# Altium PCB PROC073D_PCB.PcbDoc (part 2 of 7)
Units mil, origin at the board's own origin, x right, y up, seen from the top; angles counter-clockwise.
Board outline 2165.35 x 2695.12 mil, 8 copper layers (Top Layer, L2_GND, L3_SIGNAL 1, L4_SIGNAL 2, L5_SIGNAL 3, L6_SIGNAL 4, L7_GND, Bottom Layer), stack 56.1 mil thick; 414 components, 319 nets, 1353 pads, 1669 vias.
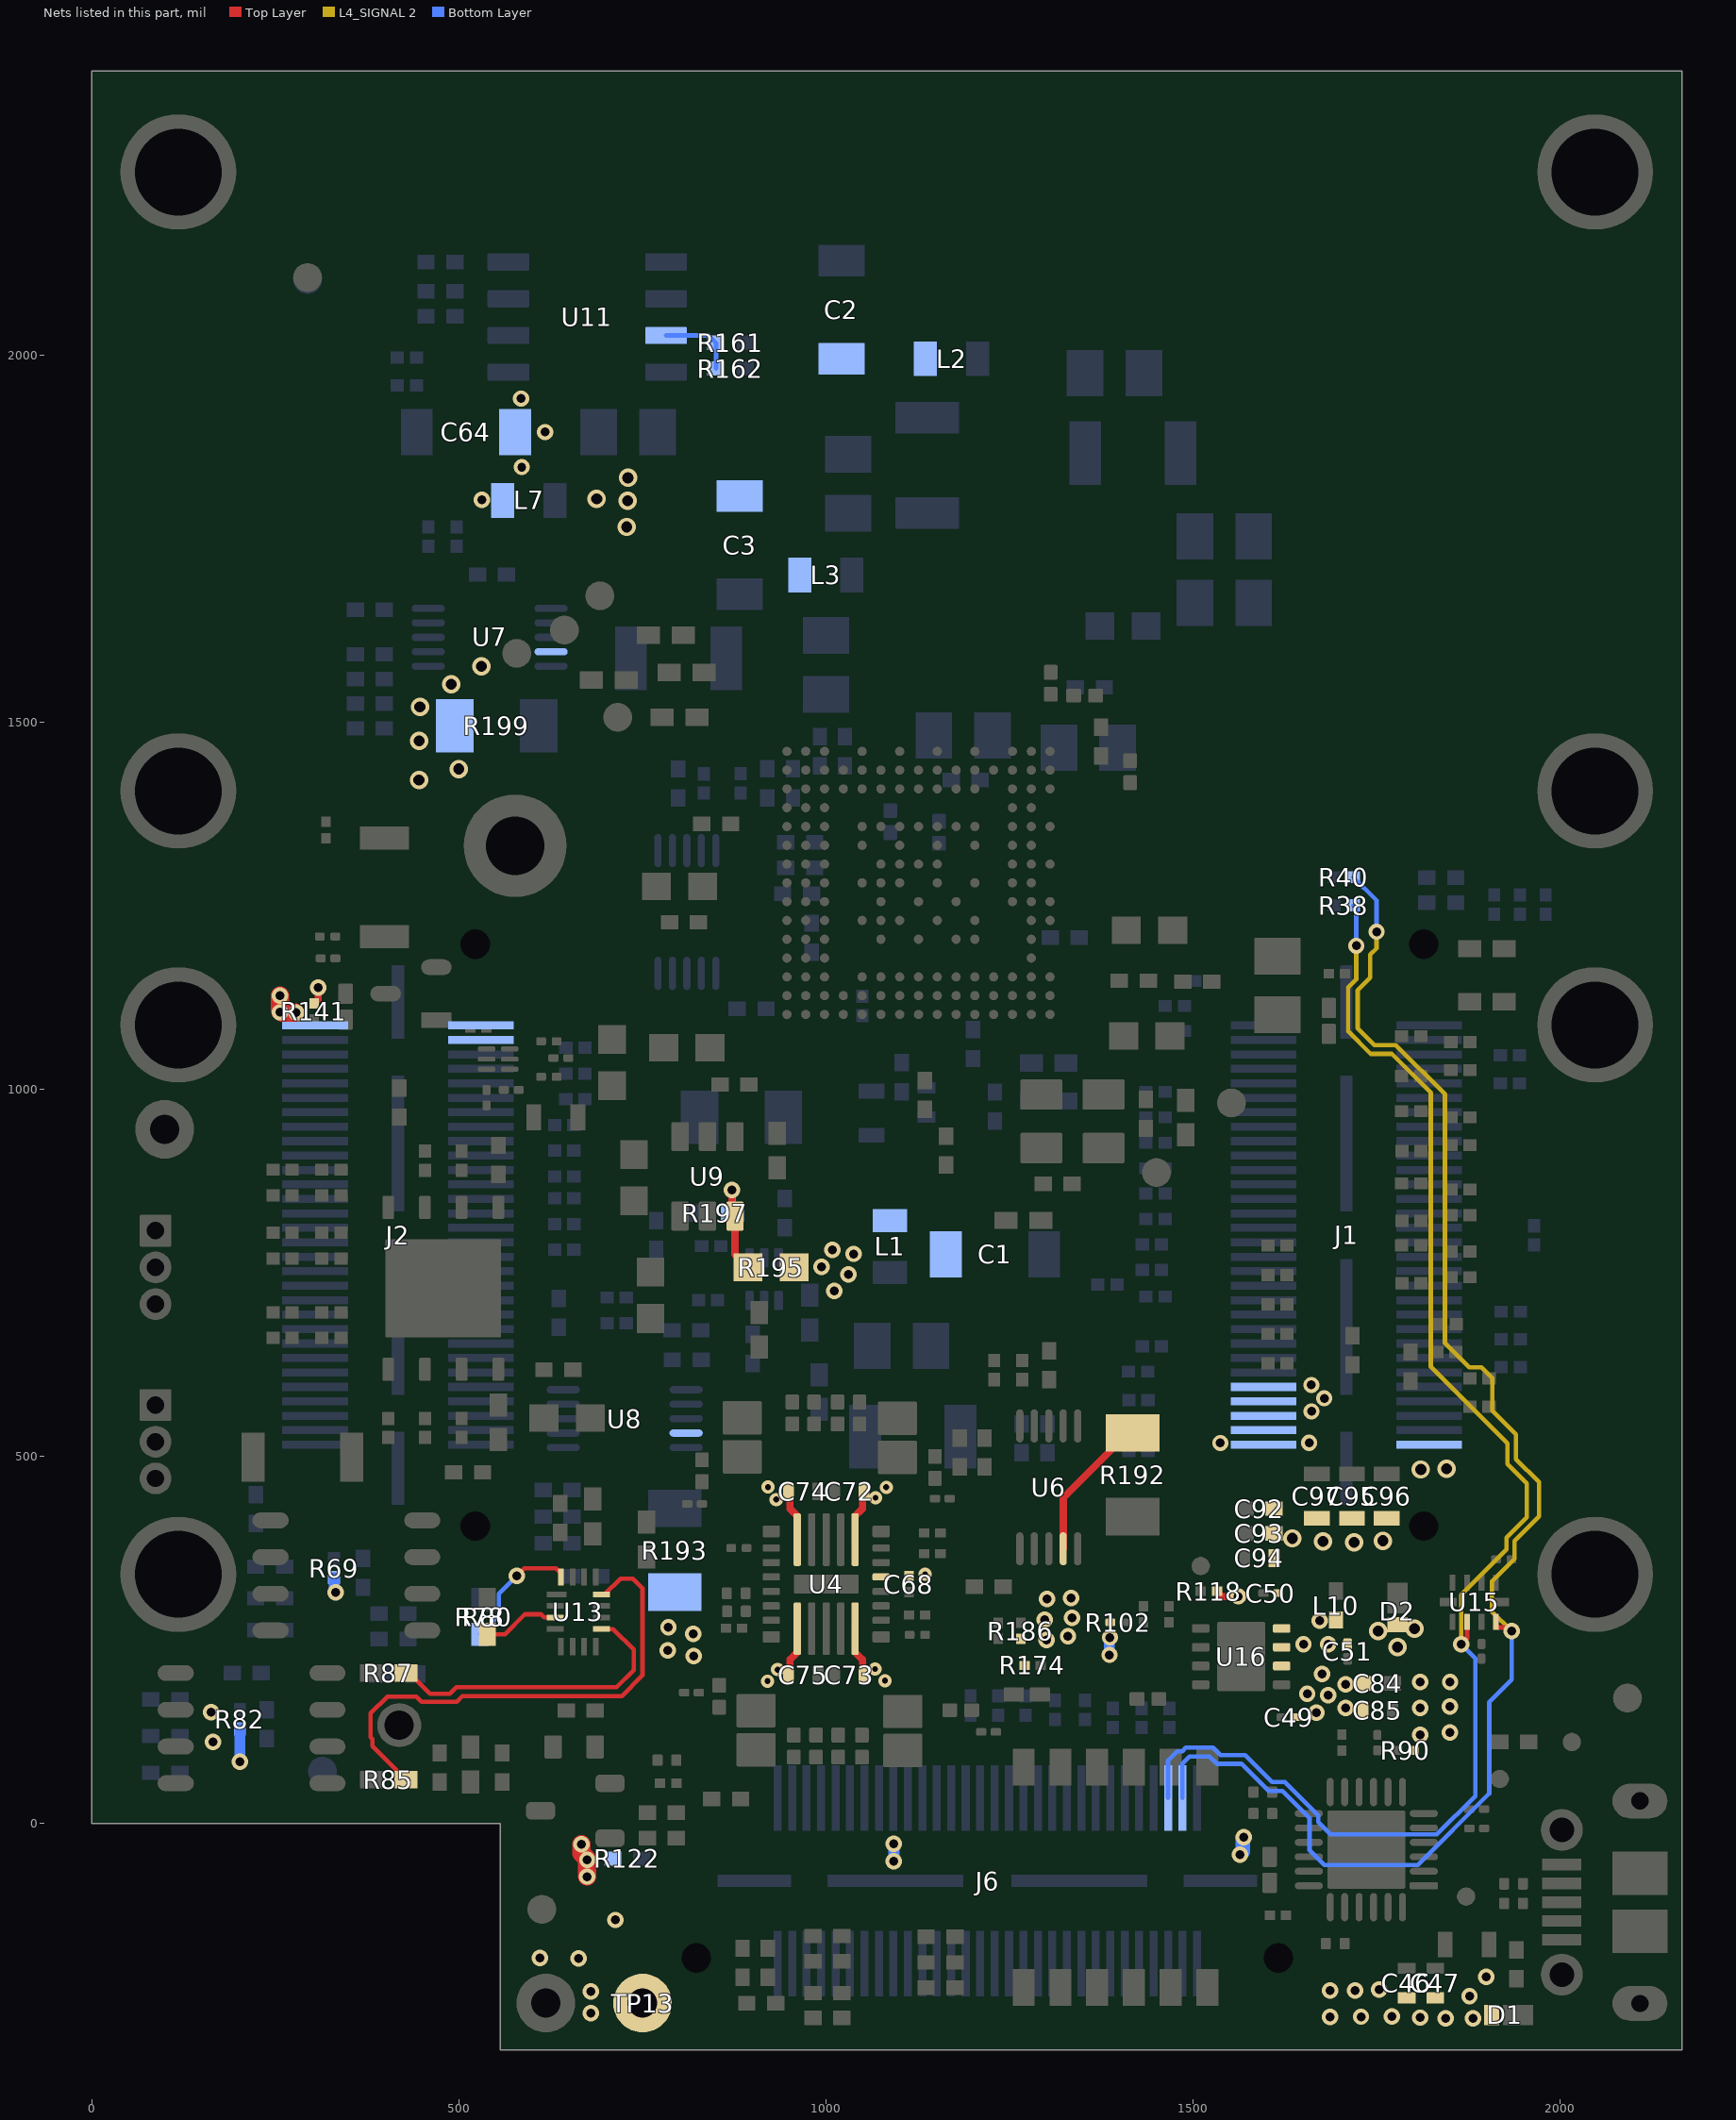
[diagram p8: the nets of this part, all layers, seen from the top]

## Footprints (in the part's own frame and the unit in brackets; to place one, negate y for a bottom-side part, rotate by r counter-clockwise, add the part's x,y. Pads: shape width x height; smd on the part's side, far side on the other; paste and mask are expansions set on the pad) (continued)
ABL0161B [mm] "BGA, 161-Balls, Body 10.4x10.4mm, Pitch 0.65mm"
  round 0.32 smd: A1(-4.55,4.55) A2(-3.9,4.55) A3(-3.25,4.55) A5(-1.95,4.55) A7(-0.65,4.55) A9(0.65,4.55) A10(1.3,4.55) A13(3.25,4.55) A14(3.9,4.55) A15(4.55,4.55) B1(-4.55,3.9) B2(-3.9,3.9) B3(-3.25,3.9) B4(-2.6,3.9) B5(-1.95,3.9) B6(-1.3,3.9) B7(-0.65,3.9) B8(0,3.9) B9(0.65,3.9) B10(1.3,3.9) B11(1.95,3.9) B12(2.6,3.9) B13(3.25,3.9) B14(3.9,3.9) B15(4.55,3.9) C1(-4.55,3.25) C2(-3.9,3.25) C3(-3.25,3.25) C4(-2.6,3.25) C5(-1.95,3.25) C6(-1.3,3.25) C7(-0.65,3.25) C8(0,3.25) C9(0.65,3.25) C13(3.25,3.25) C14(3.9,3.25) C15(4.55,3.25) D2(-3.9,2.6) D13(3.25,2.6) D14(3.9,2.6) D15(4.55,2.6) E1(-4.55,1.95) E2(-3.9,1.95) E3(-3.25,1.95) E5(-1.95,1.95) E6(-1.3,1.95) E8(0,1.95) E10(1.3,1.95) E11(1.95,1.95) E13(3.25,1.95) E14(3.9,1.95) E15(4.55,1.95) F2(-3.9,1.3) F3(-3.25,1.3) F5(-1.95,1.3) F9(0.65,1.3) F11(1.95,1.3) F13(3.25,1.3) F14(3.9,1.3) F15(4.55,1.3) G1(-4.55,0.65) G2(-3.9,0.65) G3(-3.25,0.65) G5(-1.95,0.65) G6(-1.3,0.65) G7(-0.65,0.65) G8(0,0.65) G10(1.3,0.65) G13(3.25,0.65) G14(3.9,0.65) G15(4.55,0.65) H2(-3.9,0) H3(-3.25,0) H5(-1.95,0) H7(-0.65,0) H9(0.65,0) H11(1.95,0) H13(3.25,0) H14(3.9,0) H15(4.55,0) J1(-4.55,-0.65) J2(-3.9,-0.65) J3(-3.25,-0.65) J5(-1.95,-0.65) J6(-1.3,-0.65) J7(-0.65,-0.65) J8(0,-0.65) J10(1.3,-0.65) J13(3.25,-0.65) J14(3.9,-0.65) J15(4.55,-0.65) K2(-3.9,-1.3) K3(-3.25,-1.3) K5(-1.95,-1.3) K7(-0.65,-1.3) K8(0,-1.3) K9(0.65,-1.3) K10(1.3,-1.3) K11(1.95,-1.3) K13(3.25,-1.3) K14(3.9,-1.3) K15(4.55,-1.3) L1(-4.55,-1.95) L2(-3.9,-1.95) L3(-3.25,-1.95) L5(-1.95,-1.95) L6(-1.3,-1.95) L8(0,-1.95) L10(1.3,-1.95) L13(3.25,-1.95) L14(3.9,-1.95) L15(4.55,-1.95) M2(-3.9,-2.6) M3(-3.25,-2.6) M14(3.9,-2.6) M15(4.55,-2.6) N1(-4.55,-3.25) N2(-3.9,-3.25) N3(-3.25,-3.25) N4(-2.6,-3.25) N5(-1.95,-3.25) N6(-1.3,-3.25) N7(-0.65,-3.25) N8(0,-3.25) N9(0.65,-3.25) N10(1.3,-3.25) N11(1.95,-3.25) N12(2.6,-3.25) N13(3.25,-3.25) N14(3.9,-3.25) N15(4.55,-3.25) P1(-4.55,-3.9) P2(-3.9,-3.9) P3(-3.25,-3.9) P4(-2.6,-3.9) P5(-1.95,-3.9) P6(-1.3,-3.9) P7(-0.65,-3.9) P8(0,-3.9) P9(0.65,-3.9) P10(1.3,-3.9) P11(1.95,-3.9) P12(2.6,-3.9) P13(3.25,-3.9) P14(3.9,-3.9) P15(4.55,-3.9) R1(-4.55,-4.55) R2(-3.9,-4.55) R3(-3.25,-4.55) R4(-2.6,-4.55) R5(-1.95,-4.55) R6(-1.3,-4.55) R7(-0.65,-4.55) R8(0,-4.55) R9(0.65,-4.55) R10(1.3,-4.55) R11(1.95,-4.55) R12(2.6,-4.55) R13(3.25,-4.55) R14(3.9,-4.55) R15(4.55,-4.55)
  silkscreen extent -5.3,-5.3 5.3,5.3, body extent -5.2,-5.2 5.2,5.2, height 0.62
APHHS1005_Green [mm] "SMD, 2-Leads, Body 1x0.5mm"
  rrect20% 0.7x0.5 smd: 1(-0.45,0) 2(0.45,0)
  silkscreen extent -0.8,-0.65 1.2,0.65, body extent -0.5,-0.25 0.5,0.25, height 0.5
AssemblyNote [mil] "Assembly Note"
AssemblyNoteLabel [mil] "Assembly Note for PCB Labels"
CE_Mark_5mm [mil] "Minimum text height for CE Mark"
  silkscreen extent -138,-98 138,98
CONN_105017-0001 [mm] "Molex Micro USB-B"
  rect 0.4x1.35 smd: 1(-1.3,1.35) 2(-0.65,1.35) 3(0,1.35) 4(0.65,1.35) 5(1.3,1.35)
  oval 1.2x1.9 hole 0.6 slot 1.3 at 90 deg: 6(-3.5,-1.35) 9(3.5,-1.35)
  rect 1.5x1.9 smd: 7(-1,-1.35) 8(1,-1.35)
  round 1.45 hole 0.85: 10(2.5,1.35) 11(-2.5,1.35)
  Top Layer region: 3.499,-0.399 2.299,-0.399 2.299,-2.299 3.499,-2.299
  Top Layer region: -3.5,-2.299 -2.3,-2.299 -2.3,-0.399 -3.5,-0.399
  silkscreen extent -4.1,-0.2 4.1,1.4, body extent -4.1,-3.93 4.1,1.5, height 2.72
D0008A_L [mm] "SOIC, 8-Leads, Body 4.9x3.9mm, Pitch 1.27mm, IPC High Density"
  oval 1.25x0.55 smd: 1(-2.625,1.905) 2(-2.625,0.635) 3(-2.625,-0.635) 4(-2.625,-1.905) 5(2.625,-1.905) 6(2.625,-0.635) 7(2.625,0.635) 8(2.625,1.905)
  silkscreen extent -3.1,-2.5 0.9,2.5, body extent -3,-2.45 3,2.45, height 1.63
DBV0006A_N [mm] "SOT23, 6-Leads, Body 2.9x1.6mm, Pitch 0.95mm, Lead Span 2.8mm, IPC Medium Density"
  rrect17% 1x0.6 smd: 1(-1.375,0.95) 2(-1.375,0) 3(-1.375,-0.95) 4(1.375,-0.95) 5(1.375,0) 6(1.375,0.95)
  silkscreen extent -1.68,-1.55 0.5,1.55, body extent -1.42,-1.46 1.42,1.46, height 1.12
DGS0010A_L [mm] "TSSOP, 10-Leads, Body 3x3mm, Pitch 0.5mm, IPC High Density"
  oval 1.15x0.25 smd: 1(-2.125,1) 2(-2.125,0.5) 3(-2.125,0) 4(-2.125,-0.5) 5(-2.125,-1) 6(2.125,-1) 7(2.125,-0.5) 8(2.125,0) 9(2.125,0.5) 10(2.125,1)
  silkscreen extent -2.65,-1.55 0.9,1.55, body extent -2.45,-1.5 2.45,1.5, height 0.96
DRB0008B [mm] "SON, 8-Leads, Body 3x3mm, Pitch 0.65mm, Thermal Pad 2.4x1.65mm, TI Recommended"
  rrect33% 0.6x0.3 smd: 1(-1.4,0.975) 2(-1.4,0.325) 3(-1.4,-0.325) 4(-1.4,-0.975) 5(1.4,-0.975) 6(1.4,-0.325) 7(1.4,0.325) 8(1.4,0.975)
  rrect9% 1.47x1.06 on Top Paste: 9(0,-0.63) 9(0,0.63)
  rrect6% 1.65x2.4 smd paste-1.2: 9(0,0)
  silkscreen extent -1.73,-1.73 1.73,1.73, body extent -1.5,-1.5 1.5,1.5, height 0.96
DRL0006A [mm] "SOTFL, 6-Flat Leads, Body 1.2x1.6x0.6mm, Pitch 0.5mm, TI recommended"
  rrect33% 0.67x0.3 smd: 1(-0.74,0.5) 2(-0.74,0) 3(-0.74,-0.5) 4(0.74,-0.5) 5(0.74,0) 6(0.74,0.5)
  silkscreen extent -0.9,-0.95 0.5,0.95, body extent -0.8,-0.8 0.8,0.8, height 0.61
DSF0006A [mm] "TI recommended land pattern"
  rrect59% 0.6x0.17 smd mask+0.045: 1(-0.4,0.35) 2(-0.4,0) 3(-0.4,-0.35) 4(0.4,-0.35) 5(0.4,0) 6(0.4,0.35)
  silkscreen extent -0.6,-0.63 0.6,0.63, body extent -0.5,-0.5 0.5,0.5, height 0.48
DSN2_0603 [mm] "SMD, 2-Leads, Body 1.6x0.8mm"
  rect 0.52x0.7 smd: 1(-0.64,0)
  rect 1.05x0.7 smd: 2(0.275,0)
  silkscreen extent -1.4,-0.75 0.8,0.75, body extent -0.8,-0.4 0.8,0.4, height 0.31
FCC_disclaimer [mil]
Fiducial10-20 [mm]
  round 1 smd mask+0.5: 1(0,0)
  Top Layer keep-out circle w1.178: c0,0 r0.5
FP-BSS123-7-F_SOT23-IPC_C [mm]
  rrect18% 1.059x0.547 smd paste+0 mask+0: 1(-0.877,0.915)
  rrect100% 1.059x0.547 smd paste+0 mask+0: 2(-0.877,-0.915) 3(0.877,0)
  body extent -1.51,-1.55 1.51,1.55, height 0.25
FP-CL03A105MO3NRNH_0201-IPC_C [mil]
  rrect33% 15.83x11.94 smd paste+0 mask+0: 1(-9.87,0) 2(9.87,0)
  body extent -22,-12 22,12, height 10
"FP-CL05A226MQ5N6J8_0402 (1005 Metric)-IPC_C" [mil]
  rrect21% 20.29x18.6 smd paste+0 mask+0: 1(-14.9,0) 2(14.9,0)
  body extent -20,-10 20,10, height 22
FP-CP2105-F01-GMR_QFN24-EP-IPC_A [mm]
  rrect42% 0.979x0.239 smd paste+0 mask+0: 1(-1.99,1.25)
  rrect100% 0.979x0.239 smd paste+0 mask+0: 2(-1.99,0.75) 3(-1.99,0.25) 4(-1.99,-0.25) 5(-1.99,-0.75) 6(-1.99,-1.25) 13(1.99,-1.25) 14(1.99,-0.75) 15(1.99,-0.25) 16(1.99,0.25) 17(1.99,0.75) 18(1.99,1.25)
  rrect100% 0.239x0.979 smd paste+0 mask+0: 7(-1.25,-1.99) 8(-0.75,-1.99) 9(-0.25,-1.99) 10(0.25,-1.99) 11(0.75,-1.99) 12(1.25,-1.99) 19(1.25,1.99) 20(0.75,1.99) 21(0.25,1.99) 22(-0.25,1.99) 23(-0.75,1.99) 24(-1.25,1.99)
  rrect4% 2.7x2.7 smd paste-1000 mask+0: 25(0,0)
  body extent -2.98,-2.98 2.98,2.98, height 0.25
FP-CRCW0402200RFKEDHP_0402-IPC_C [mil]
  rrect21% 20.29x18.6 smd paste+0 mask+0: 1(-14.9,0) 2(14.9,0)
  body extent -20,-10 20,10, height 16
"FP-GRM033R6YA104KE14D_0201 (0603 Metric)-IPC_C" [mil]
  rrect38% 13.94x10.34 smd paste+0 mask+0: 1(-10.01,0) 2(10.01,0)
  body extent -21,-10 21,10, height 10
FP-M50-3930342_HDR3-MFG [mm]
  rrect9% 1.1x1.1 hole 0.6 paste-1000 mask+0: 1(-1.27,1)
  round 1.1 hole 0.6 paste-1000 mask+0: 2(0,1) 3(1.27,1)
  silkscreen extent -2.97,-0.6 2.15,1.12, body extent -2.25,-4.9 2.25,1.65, height 0.25
"FP-MCKK2012TR47M_0805 (2012 Metric)-IPC_C" [mil]
  rrect9% 45.45x53.39 smd paste+0 mask+0: 1(-26.61,0) 2(26.61,0)
  body extent -53,-32 53,32, height 10
"FP-RC0201JR-070RL_0201 (0603 Metric)-IPC_C" [mil]
  rrect38% 13.94x10.34 smd paste+0 mask+0: 1(-10.01,0) 2(10.01,0)
  body extent -21,-10 21,10, height 10
"FP-RC0201JR-070RL_0201 (0603 Metric)-MFG" [mm]
  rrect29% 0.35x0.4 smd paste+0 mask+0: 1(-0.325,0) 2(0.325,0)
  body extent -0.3,-0.15 0.3,0.15, height 0.26
"FP-RC0402FR-073R83L_0402 (1005 Metric)-IPC_C" [mil]
  rrect21% 20.29x18.6 smd paste+0 mask+0: 1(-14.9,0) 2(14.9,0)
  body extent -29,-15 29,15, height 10
FP-RR0306P-103-D_0201-IPC_C [mil]
  rrect37% 13.31x10.73 smd paste+0 mask+0: 1(-10.52,0) 2(10.52,0)
  body extent -12,-6 12,6, height 10
"FP-TMK063CG391JT-F_0201 (0603 Metric)-IPC_C" [mil]
  rrect38% 13.94x10.34 smd paste+0 mask+0: 1(-10.01,0) 2(10.01,0)
  body extent -21,-10 21,10, height 10
IEC_HotSurface_Small [mil]
  silkscreen extent -107,-93 107,92
Keystone5001 [mil] "For Keystone 500x miniature loop terminals"
  round 80 hole 40: 1(0,0)
  silkscreen extent -52,-52 52,52, body extent -49,-49 49,49, height 182
Kyocera_CX3225SA [mm] "SMD, 4-Leads, Body 3.2x2.5mm"
  rrect10% 1.05x1.45 smd: 1(-0.925,1.075) 2(-0.925,-1.075) 3(0.925,-1.075) 4(0.925,1.075)
  silkscreen extent -1,2.28 -0.87,2.4, body extent -1.3,-1.65 1.3,1.65, height 0.9
Label_650x200 [mil] "Thermal Transfer Label"
  round 1 on Mech13: 0(0,0)
  silkscreen extent -325,-100 325,100, body extent -325,-100 325,100, height 1
MPZ2012 [mm] "TDK"
  rect 0.8x1.2 smd: 1(-0.9,0) 2(0.9,0)
  body extent -1.1,-0.72 1.1,0.72, height 1.05
RNF0026C [mm] "QFN, 26-Leads, Body 4x4.5mm, Pitch 0.5mm"
  rrect25% 0.6x0.4 smd paste-0.3: 1(-1.9,1.825) 8(-1.9,-1.825) 14(1.9,-1.825) 21(1.9,1.825)
  rrect40% 0.6x0.25 smd paste+0: 2(-1.9,1.25) 3(-1.9,0.75) 4(-1.9,0.25) 5(-1.9,-0.25) 6(-1.9,-0.75) 7(-1.9,-1.25) 15(1.9,-1.25) 16(1.9,-0.75) 17(1.9,-0.25) 18(1.9,0.25) 19(1.9,0.75) 20(1.9,1.25)
  rrect40% 0.25x1.82 smd paste-1: 9(-1,-1.54) 10(-0.5,-1.54) 11(0,-1.54) 12(0.5,-1.54) 13(1,-1.54) 22(1,1.54) 23(0.5,1.54) 24(0,1.54) 25(-0.5,1.54) 26(-1,1.54)
  rrect15% 2.24x0.66 smd paste-1: 27(0,0)
  rrect33% 0.6x0.3 on Top Paste: ""(-1.9,-1.775) ""(-1.9,1.775) ""(1.9,-1.775) ""(1.9,1.775)
  rrect33% 0.3x0.825 on Top Paste: ""(-1.575,-2.037) ""(-1.575,2.037) ""(1.575,-2.037) ""(1.575,2.037)
  rrect40% 0.25x0.81 on Top Paste: ""(-1,2.045) ""(-1,-2.045) ""(-1,-1.035) ""(-1,1.035) ""(-0.5,2.045) ""(-0.5,-2.045) ""(-0.5,-1.035) ""(-0.5,1.035) ""(0,1.035) ""(0,-2.045) ""(0,-1.035) ""(0,2.045) ""(0.5,-2.045) ""(0.5,-1.035) ""(0.5,2.045) ""(0.5,1.035) ""(1,-2.045) ""(1,-1.035) ""(1,1.035) ""(1,2.045)
  rrect15% 0.98x0.66 on Top Paste: ""(-0.59,0) ""(0.59,0)
  Top Layer region: -1.775,1.675 -1.775,2.4 -1.771,2.419 -1.76,2.435 -1.744,2.446 -1.725,2.45 -1.725,2.45 -1.475,2.45 -1.456,2.446 -1.44,2.435 -1.429,2.419 -1.425,2.4 -1.425,2.4 -1.425,1.675 -1.429,1.656 -1.44,1.64 -1.456,1.629 -1.475,1.625 -1.475,1.625 -1.725,1.625 -1.744,1.629 -1.76,1.64 -1.771,1.656 -1.775,1.675
  Top Layer region: 1.425,1.675 1.425,2.4 1.429,2.419 1.44,2.435 1.456,2.446 1.475,2.45 1.475,2.45 1.725,2.45 1.744,2.446 1.76,2.435 1.771,2.419 1.775,2.4 1.775,2.4 1.775,1.675 1.771,1.656 1.76,1.64 1.744,1.629 1.725,1.625 1.725,1.625 1.475,1.625 1.456,1.629 1.44,1.64 1.429,1.656 1.425,1.675
  Top Layer region: 1.425,-2.4 1.425,-1.675 1.429,-1.656 1.44,-1.64 1.456,-1.629 1.475,-1.625 1.475,-1.625 1.725,-1.625 1.744,-1.629 1.76,-1.64 1.771,-1.656 1.775,-1.675 1.775,-1.675 1.775,-2.4 1.771,-2.419 1.76,-2.435 1.744,-2.446 1.725,-2.45 1.725,-2.45 1.475,-2.45 1.456,-2.446 1.44,-2.435 1.429,-2.419 1.425,-2.4
  Top Layer region: -1.775,-2.4 -1.775,-1.675 -1.771,-1.656 -1.76,-1.64 -1.744,-1.629 -1.725,-1.625 -1.725,-1.625 -1.475,-1.625 -1.456,-1.629 -1.44,-1.64 -1.429,-1.656 -1.425,-1.675 -1.425,-1.675 -1.425,-2.4 -1.429,-2.419 -1.44,-2.435 -1.456,-2.446 -1.475,-2.45 -1.475,-2.45 -1.725,-2.45 -1.744,-2.446 -1.76,-2.435 -1.771,-2.419 -1.775,-2.4
  silkscreen extent -2.45,-2.7 2.45,2.7, body extent -2,-2.25 2,2.25, height 0.9
RSE0010A [mm] "QFN, 10-Leads, Body 1.5x2mm, Pitch 0.5mm, TI Recommended"
  rect 0.55x0.2 smd: 1(-0.675,0.75) 2(-0.675,0.25) 3(-0.675,-0.25) 4(-0.675,-0.75) 6(0.675,-0.75) 7(0.675,-0.25) 8(0.675,0.25) 9(0.675,0.75)
  rect 0.3x0.6 smd: 5(0,-0.9) 10(0,0.9)
  silkscreen extent -1.07,-1.18 0.78,1.18, body extent -0.77,-1.02 0.78,1.03, height 0.61
RSV0016A [mm] "QFN, 16-Leads, Body 1.8x2.6mm, Pitch 0.4mm, TI Recommended"
  rect 0.7x0.2 smd: 1(-0.75,0.6)
  rect 0.6x0.2 smd: 2(-0.8,0.2) 3(-0.8,-0.2) 4(-0.8,-0.6) 9(0.8,-0.6) 10(0.8,-0.2) 11(0.8,0.2) 12(0.8,0.6)
  rect 0.2x0.6 smd: 5(-0.6,-1.2) 6(-0.2,-1.2) 7(0.2,-1.2) 8(0.6,-1.2) 13(0.6,1.2) 14(0.2,1.2) 15(-0.2,1.2) 16(-0.6,1.2)
  silkscreen extent -1.08,-1.33 1.08,1.45, body extent -0.92,-1.32 0.93,1.33, height 0.56
Samtec_QSH-030-01-X-D-A [mm] "Receptacle, 0.5 mm, 30x2, TH"
  rect 2.27x0.279 smd: 1(-2.865,7.25) 2(2.865,7.25) 3(-2.865,6.75) 4(2.865,6.75) 5(-2.865,6.25) 6(2.865,6.25) 7(-2.865,5.75) 8(2.865,5.75) 9(-2.865,5.25) 10(2.865,5.25) 11(-2.865,4.75) 12(2.865,4.75) 13(-2.865,4.25) 14(2.865,4.25) 15(-2.865,3.75) 16(2.865,3.75) 17(-2.865,3.25) 18(2.865,3.25) 19(-2.865,2.75) 20(2.865,2.75) 21(-2.865,2.25) 22(2.865,2.25) 23(-2.865,1.75) 24(2.865,1.75) 25(-2.865,1.25) 26(2.865,1.25) 27(-2.865,0.75) 28(2.865,0.75) 29(-2.865,0.25) 30(2.865,0.25) 31(-2.865,-0.25) 32(2.865,-0.25) 33(-2.865,-0.75) 34(2.865,-0.75) 35(-2.865,-1.25) 36(2.865,-1.25) 37(-2.865,-1.75) 38(2.865,-1.75) 39(-2.865,-2.25) 40(2.865,-2.25) 41(-2.865,-2.75) 42(2.865,-2.75) 43(-2.865,-3.25) 44(2.865,-3.25) 45(-2.865,-3.75) 46(2.865,-3.75) 47(-2.865,-4.25) 48(2.865,-4.25) 49(-2.865,-4.75) 50(2.865,-4.75) 51(-2.865,-5.25) 52(2.865,-5.25) 53(-2.865,-5.75) 54(2.865,-5.75) 55(-2.865,-6.25) 56(2.865,-6.25) 57(-2.865,-6.75) 58(2.865,-6.75) 59(-2.865,-7.25) 60(2.865,-7.25)
  round 0 hole 1.02 unplated mask+0.127: MH1(2.67,10.065) MH2(2.67,-10.065)
  rect 0.43x2.54 smd: MP1(0,8.065) MP4(0,-8.065)
  rect 0.43x4.7 smd: MP2(0,3.175) MP3(0,-3.175)
  silkscreen extent -3.9,-10.66 3.62,10.66, body extent -3.75,-10.64 3.75,10.67, height 3.25
SOIC-8 [mm] "duplicate of SO-8.  SOIC, 8-Leads, Body 5.0x4.0mm (max), Pitch 1.27mm, IPC Medium Density"
  rrect17% 1.45x0.6 smd: 1(-2.725,1.905) 2(-2.725,0.635) 3(-2.725,-0.635) 4(-2.725,-1.905) 5(2.725,-1.905) 6(2.725,-0.635) 7(2.725,0.635) 8(2.725,1.905)
  silkscreen extent -3.5,-2.5 0.9,2.5, body extent -3,-2.45 3,2.45, height 1.63
SOT-23 [mm] "SOT23, 3-Leads, Body 2.9x1.3mm, Pitch 0.95mm, Lead Span 2.5mm, IPC Medium Density"
  rrect50% 1x0.6 smd: 1(-1.2,0.95) 2(-1.2,-0.95) 3(1.2,0)
  silkscreen extent -1.62,-1.5 0.7,1.5, body extent -1.16,-1.45 1.21,1.45, height 1
SW_218-6LPST [mm] "SMD, 12-Leads, Body 5.8x8.79mm"
  rect 1.27x0.76 smd: 1(-3.81,3.175) 2(-3.81,1.905) 3(-3.81,0.635) 4(-3.81,-0.635) 5(-3.81,-1.905) 6(-3.81,-3.175) 7(3.81,-3.175) 7(3.81,-3.175) 8(3.81,-1.905) 9(3.81,-0.635) 10(3.81,0.635) 11(3.81,1.905) 12(3.81,3.175)
  silkscreen extent -2.9,-4.4 2.9,4.7, body extent -4.22,-4.4 4.22,4.39, height 2.62
SW_B3U-1000P [mm] "OMRON"
  rect 0.8x1.7 smd: 1(-1.7,0) 2(1.7,0)
  silkscreen extent -1.5,-1.25 1.5,1.25, body extent -1.5,-1.25 1.5,1.25, height 1.75
TI_Stacked_Overlay_Small [mil]
  silkscreen extent -418,-78 -237,98
TI_Symbol_Overlay_Small [mil]
  silkscreen extent -90,-88 91,88
TLMx1000_Yellow [mm] "SMD, 2-Leads, Body 1.6x0.8mm"
  rrect17% 0.6x0.8 smd: 1(-0.725,0) 2(0.725,0)
  silkscreen extent -0.98,-0.8 1.6,0.8, body extent -0.85,-0.45 0.85,0.45, height 0.65
TP_25MIL-SMT [mil]
  round 25 smd mask-2.5: 1(0,0)
TP_SM_1MM [mm] "1mm Test Point, SMT"
  round 1 smd paste-0.5: 1(0,0)
TP_VIA_060RND040 [mil] "TP_VIA_060RND040"
  round 60 hole 40: 1(0,0)
WEEE_Minimum [mil] "WEEElie bin"
  silkscreen extent -95,-172 99,104
WSON-8L_6x5MM_EP [mm] "SMD, 8-Leads, Body 6x5mm, Pitch 1.27mm"
  rrect25% 0.8x0.4 smd: 1(-2.8,1.905) 2(-2.8,0.635) 3(-2.8,-0.635) 4(-2.8,-1.905) 5(2.8,-1.905) 6(2.8,-0.635) 7(2.8,0.635) 8(2.8,1.905)
  rrect3% 3.4x4 smd paste-3: 9(0,0)
  rrect7% 1.468x1.698 on Top Paste: ""(-0.834,0.949) ""(-0.834,-0.949) ""(0.834,0.949) ""(0.834,-0.949)
  silkscreen extent -3.2,-2.7 3.2,2.7, body extent -3.05,-2.55 3.05,2.55, height 0.8

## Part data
C1 C2 C3 C64: library part CMP-0008770-2, "CAP, CERM, 22 uF, 6.3 V, +/- 10%, X7R, AEC-Q200 Grade 1, 1206", Cap_Case=1206_180, Manufacturer=TDK, Supplier Part Number 1=445-7884-1-ND, TempCo=X7R, Tolerance_%=10%, Value1="0.001872 ohm", Value2=6.3V, ValueDisplayed=22uF
C4 C5 C9 C10 C11 C12 C14 C16 C19 C20 C21 C28 C29: library part CMP-0078265-1, "CAP, CERM, 0.22 µF, 16 V,+/- 10%, X7R, AEC-Q200 Grade 1, 0402", Cap_Case=0402, Manufacturer=MuRata, Supplier Part Number 1=490-10671-1-ND, TempCo=X7R, Tolerance_%=10%, Value2=16V, ValueDisplayed=0.22µF
C6: library part CMP-0006330-2, "CAP, CERM, 0.047 uF, 50 V, +/- 10%, X7R, AEC-Q200 Grade 1, 0402", Cap_Case=0402, Manufacturer=TDK, Supplier Part Number 1=445-6897-1-ND, TempCo=X7R, Tolerance_%=10%, Value1="0.06407 ohm", Value2=50V, ValueDisplayed=0.047uF
C7 C8 C13 C15 C23 C24: library part CMP-0085348-1, "CAP, CERM, 10 µF, 10 V,+/- 20%, X7R, 0805", Cap_Case=0805, Manufacturer=Kemet, TempCo=X7R, Tolerance_%=20%, Value2=10V, ValueDisplayed=10µF
C17 C27: library part CMP-0007134-5, "CAP, CERM, 2.2 uF, 6.3 V, +/- 10%, X7R, AEC-Q200 Grade 1, 0603", Cap_Case=0603, Manufacturer=MuRata, Supplier Part Number 1=490-5316-1-ND, TempCo=X7R, Tolerance_%=10%, Value1=Unknown, Value2=6.3V, ValueDisplayed=2.2uF
C18 C22 C35: library part CMP-0007136-5, "CAP, CERM, 1 uF, 16 V, +/- 10%, X7R, AEC-Q200 Grade 1, 0603", Cap_Case=0603, Manufacturer=MuRata, Supplier Part Number 1=490-5241-6-ND, TempCo=X7R, Tolerance_%=10%, Value1=Unknown, Value2=16V, ValueDisplayed=1uF
C25 C26: library part CMP-0006351-2, "CAP, CERM, 0.1 uF, 16 V, +/- 10%, X7R, 0402", Cap_Case=0402, Manufacturer=MuRata, Supplier Part Number 1=490-4759-2-ND, TempCo=X7R, Tolerance_%=10%, Value1=Unknown, Value2=16V, ValueDisplayed=0.1uF
C30: library part CMP-0006352-2, "CAP, CERM, 0.01 uF, 25 V, +/- 10%, X7R, 0402", Cap_Case=0402, Manufacturer=MuRata, Supplier Part Number 1=490-6043-2-ND, TempCo=X7R, Tolerance_%=10%, Value1=Unknown, Value2=25V, ValueDisplayed=0.01uF
C31: library part CMP-0064969-1, "CAP, CERM, 0.1 uF, 10 V,+/- 10%, X7S, 0201", Cap_Case=0201, Manufacturer=MuRata, Supplier Part Number 1=490-14450-1-ND, TempCo=X7S, Tolerance_%=10%, Value1=Unknown, Value2=10V, ValueDisplayed=0.1uF
C32 C33: library part CMP-0006367-2, "CAP, CERM, 4.7 pF, 50 V, +/- 2%, C0G/NP0, 0402", Cap_Case=0402, Manufacturer=MuRata, Supplier Part Number 1=490-8102-1-ND, TempCo=C0G/NP0, Tolerance_%=2%, Value1=Unknown, Value2=50V, ValueDisplayed=4.7pF
C34 C36 C57 C58 C59 C63 C65: library part CMP-0006325-2, "CAP, CERM, 0.1 uF, 50 V, +/- 10%, X7R, AEC-Q200 Grade 1, 0402", Cap_Case=0402, Manufacturer=TDK, Supplier Part Number 1=445-6899-1-ND, TempCo=X7R, Tolerance_%=10%, Value1="0.039064 ohm", Value2=50V, ValueDisplayed=0.1uF
C37 C38 C40 C41 C43: library part CMP-0078241-1, "CAP, CERM, 0.1 µF, 10 V,+/- 10%, X7R, 0402", Cap_Case=0402, Manufacturer=Kemet, Supplier Part Number 1=399-3520-1-ND, TempCo=X7R, Tolerance_%=10%, Value2=10V, ValueDisplayed=0.1µF
C39 C42: library part CMP-0006361-2, "CAP, CERM, 4700 pF, 50 V, +/- 10%, X7R, AEC-Q200 Grade 1, 0402", Cap_Case=0402, Manufacturer=MuRata, Supplier Part Number 1=490-4915-1-ND, TempCo=X7R, Tolerance_%=10%, Value1=Unknown, Value2=50V, ValueDisplayed=4700pF
C44 C45 C48 C49 C50 C52 C53: library part CMP-0086440-1, "Cap Ceramic 0.1uF 35V X5R 10% Pad SMD 0201 85C T/R", Manufacturer="Murata Electronics North America", TempCo=15%, Tolerance_%=10%
C46 C47 C72 C73 C74 C75: library part CMP-0006339-4, "CAP, CERM, 10 uF, 10 V, +/- 20%, X5R, 0402", Cap_Case=0402, Manufacturer="Samsung Electro-Mechanics", TempCo=X5R, Tolerance_%=20%, Value1=Unknown, Value2=10V, ValueDisplayed=10uF
C51: library part CMP-0086446-1, "1µF ±20% 16V Ceramic Capacitor X5R 0201", Manufacturer="Samsung Electro-Mechanics", TempCo=15%, Tolerance_%=20%
C54 C55 C56 C60: library part CMP-0086438-1, "CAP CER 390PF 25V C0G/NP0 0201", Manufacturer="Taiyo Yuden", TempCo=30ppm/°C, Tolerance_%=5%
C61 C62 C66 C67 C90 C91 C98 C99 C100 C101 C102 C103 C104: library part CMP-0086447-1, "CAP CER 22UF 6.3V X5R 0402", Manufacturer="Samsung Electro-Mechanics", TempCo=15%, Tolerance_%=20%
C68: library part CMP-0009781-1, "CAP, CERM, 0.22 uF, 10 V, +/- 20%, X5R, 0201", Cap_Case=0201, Manufacturer="Taiyo Yuden", Supplier Part Number 1=587-2483-1-ND, TempCo=X5R, Tolerance_%=20%, Value1=Unknown, Value2=10V, ValueDisplayed=0.22uF
C69: library part CMP-0007111-4, "CAP, CERM, 1 uF, 6.3 V, +/- 10%, X7R, 0603", Cap_Case=0603, Manufacturer="Samsung Electro-Mechanics", TempCo=X7R, Tolerance_%=10%, Value1=Unknown, Value2=6.3V, ValueDisplayed=1uF
C70: library part CMP-0006858-4, "CAP, CERM, 0.1 uF, 50 V, +/- 5%, X7R, 0603", Cap_Case=0603, Manufacturer=Kemet, Supplier Part Number 1=399-7844-1-ND, TempCo=X7R, Tolerance_%=5%, Value1=Unknown, Value2=50V, ValueDisplayed=0.1uF
C71: library part CMP-0006332-2, "CAP, CERM, 1000 pF, 100 V, +/- 10%, X7S, AEC-Q200 Grade 1, 0402", Cap_Case=0402, Manufacturer=TDK, Supplier Part Number 1=445-6904-1-ND, TempCo=X7S, Tolerance_%=10%, Value1="2.71151 ohm", Value2=100V, ValueDisplayed=1000pF
C76 C78 C80 C82: library part CMP-0009174-2, "CAP, CERM, 22 uF, 16 V, +/- 10%, X7R, 1210", Cap_Case=1210, Manufacturer=MuRata, Supplier Part Number 1=490-5242-1-ND, TempCo=X7R, Tolerance_%=10%, Value1=Unknown, Value2=16V, ValueDisplayed=22uF
C77 C79 C81 C83: library part CMP-0008017-2, "CAP, CERM, 10 uF, 10 V, +/- 10%, X7R, 0805", Cap_Case=0805, Manufacturer=MuRata, Supplier Part Number 1=490-10674-1-ND, TempCo=X7R, Tolerance_%=10%, Value1=Unknown, Value2=10V, ValueDisplayed=10uF
C84 C92: library part CMP-0064967-2, "CAP, CERM, 0.47 uF, 10 V,+/- 10%, X7S, 0402", Cap_Case=0402, Manufacturer=MuRata, Supplier Part Number 1=490-14427-1-ND, TempCo=X7S, Tolerance_%=10%, Value1=Unknown, Value2=10V, ValueDisplayed=0.47uF
C85 C89 C94: library part CMP-0006262-2, "CAP, CERM, 0.22 uF, 10 V, +/- 10%, X7R, 0402", Cap_Case=0402, Manufacturer=TDK, Supplier Part Number 1=445-4985-1-ND, TempCo=X5R, Tolerance_%=10%, Value1=Unknown, Value2=10V, ValueDisplayed=0.22uF
C86 C87 C88 C95 C96 C97: library part CMP-0007497-5, "CAP, CERM, 10 uF, 10 V, +/- 10%, X5R, 0603", Cap_Case=0603, Manufacturer=MuRata, Supplier Part Number 1=81-GRM188Z71A106MA3D, TempCo=X7R, Tolerance_%=20%, Value1=Unknown, Value2=10V, ValueDisplayed=10uF
C93: library part CMP-0006272-2, "CAP, CERM, 1 uF, 10 V, +/- 10%, X6S, 0402", Cap_Case=0402, Manufacturer=TDK, Supplier Part Number 1=445-4978-1-ND, TempCo=X5R, Tolerance_%=10%, Value1=Unknown, Value2=16V, ValueDisplayed=1uF
"CAUTION HOT SURFACE1": library part CMP-0074837-1, "IEC 61010-1 Hot Surface Warning"
D1 D2: library part CMP-0028829-2, "Diode, Schottky, 30 V, 2 A, 2-XFDFN", Manufacturer="ON Semiconductor", Value1=2A, Value2=0.48V
D3: library part CMP-0078196-2, "LED, Yellow, SMD", Color=yellow, Manufacturer=Vishay-Semiconductor, Power_TotalModule=40mW, Value1=.04W, Value2=1.8V
D4 D5 D6 D7: library part CMP-0067682-2, "LED, Green, SMD", Color=Green, Manufacturer=Kingbright, Power_TotalModule=75mW, Value1=0.075W, Value2=2.1V
FID1 FID2 FID3 FID4 FID5 FID6: library part CMP-0077181-1, "Fiducial mark.  There is nothing to buy or mount.", Manufacturer=N/A
J1 J2 J6: library part CMP-0075524-1, "Receptacle, 0.5 mm, 30x2, Gold, TH", Color=Black, Manufacturer=Samtec, Supplier Part Number 1=SAM8180-ND
J3 J4: library part CMP-0087785-1, "CONN HEADER R/A 3POS 1.27MM", Current_A=1A, Manufacturer=Harwin
J5: library part CMP-0055293-1, "Connector, Receptacle, Micro-USB Type B, R/A, Bottom Mount SMT", Manufacturer=Molex, Supplier Part Number 1=WM1399CT-ND
L1 L2 L3 L7: library part CMP-0003427-2, "Ferrite Bead, 100 ohm @ 100 MHz, 4 A, 0805", Manufacturer=TDK, Value1="0.02 ohm", Value2=4A, ValueDisplayed="100 ohm"
L4 L5 L6 L8: library part CMP-0087178-1, "FIXED IND 470NH 4.5A 39 MOHM SMD", Manufacturer="Taiyo Yuden"
L9 L10 L11 L12: library part CMP-0078934-1, "Inductor, Ferrite Bead, Ferrite, 2.2 A, 0.035 ohm, AEC-Q200 Grade 1, SMD", Manufacturer=MuRata, Supplier Part Number 1=490-16506-1-ND, Value1="0.035 ohm", Value2=2.2A
LBL1: library part CMP-0003625-1, "Thermal Transfer Printable Labels, 0.650\" W x 0.200\" H - 10,000 per roll", Manufacturer=Brady, Supplier Part Number 1=97C5133
Logo1 Logo5: library part CMP-0074838-1, "Texas Instrument Corporate Signature"
Logo2: library part CMP-0074844-1
LOGO3: library part CMP-0074847-1, "FCC_disclaimer"
Logo4: library part CMP-0074769-1
Q1: library part CMP-0087176-1, "MOSFET N-CH 100V 170MA SOT23-3", Manufacturer="Diodes Incorporated"
Q2: library part CMP-0000947-2, "MOSFET, N-CH, 100 V, 0.17 A, SOT-23", Alternate Manufacturer=None, Manufacturer="Fairchild Semiconductor", Supplier Part Number 1=BSS123NCT-ND, Value1=1, Value2="1.8 nC"
R1 R195: library part CMP-0025884-3, "RES, 0, 5%, 0.125 W, 0603", Manufacturer=Vishay/Beyschlag, Power_W=125mW, Supplier Part Number 1=MCT0603-0.0-ZZCT-ND, TempCo=ppm/C, Tolerance_%=5%, Value2=0.125W, Value_Code=0000, ValueDisplayed=0
R2 R14 R44 R49 R52 R53 R54 R70 R71 R83 R84 R88 R94 R101 R103 R104 R105 R106 R107 R112 R113 R114 R115 R116 R117 R139 R142 R145 R146 R147 R152 R157 R158 R161 R162 R203 R206 R209: library part CMP-0025958-3, "RES, 10.0 k, 1%, 0.063 W, AEC-Q200 Grade 0, 0402", Manufacturer=Vishay-Dale, Power_W=63mW, Supplier Part Number 1=541-10.0KLCT-ND, TempCo="100 ppm/C", Tolerance_%=1%, Value2=0.063W, Value_Code=10k0, ValueDisplayed=10.0k
R3 R43 R72 R73 R74 R75 R76 R77 R78 R80 R85 R87 R122 R202 R216: library part CMP-0026992-3, "RES, 0, 5%, 0.1 W, AEC-Q200 Grade 0, 0402", Manufacturer=Panasonic, Power_W=100mW, Supplier Part Number 1=P0.0JCT-ND, TempCo="600 ppm/C", Tolerance_%=5%, Value2=0.1W, Value_Code=0000, ValueDisplayed=0
R4 R5 R6 R7 R8 R9 R10 R11 R12 R13 R16 R22 R24 R25 R29 R30 R31 R32 R33 R34 R35 R36 R37 R38 R39 R40 R41 R42 R55 R56 R58 R59 R60 R61 R62 R63 R64 R65 R66 R67 R69 R82 R108 R109 R110 R111 R131 R133 R134 R135 R136 R137 R140 R143 R144 R159 R160 R217 R218 R219 R220 R221 R222 R223 R224 R225 R226 R227 R228 R229 R230: library part CMP-0027008-4, "RES, 0, 5%, 0.05 W, 0201", Manufacturer=Vishay-Dale, Power_W=50mW, Supplier Part Number 1=72M6743, TempCo=ppm/C, Tolerance_%=5%, Value2=0.05W, Value_Code=0000, ValueDisplayed=0
R15 R17 R18 R19 R20 R21 R23 R26 R27 R28 R124 R125 R126 R127 R128 R129 R130 R132 R148 R149 R163 R164 R166 R167 R168 R170: library part CMP-0078192-2, "RES, 20.0, 1%, 0.05 W, 0201", Manufacturer=Vishay-Dale, Power_W=50mW, Supplier Part Number 1=541-2947-1-ND, TempCo="200 ppm/C", Tolerance_%=1%, Value2=0.05W, Value_Code=20R0, ValueDisplayed=20.0
R45 R46 R47 R48 R51: library part CMP-0027275-3, "RES, 33.2, 1%, 0.05 W, 0201", Manufacturer=Vishay-Dale, Power_W=50mW, Supplier Part Number 1=541-33.2ABCT-ND, TempCo="200 ppm/C", Tolerance_%=1%, Value2=0.05W, Value_Code=33R2, ValueDisplayed=33.2
R50: library part CMP-0026395-2, "RES, 47.5 k, 1%, 0.063 W, AEC-Q200 Grade 0, 0402", Manufacturer=Vishay-Dale, Power_W=63mW, Supplier Part Number 1=541-47.5KLCT-ND, TempCo="100 ppm/C", Tolerance_%=1%, Value2=0.063W, Value_Code=47k5, ValueDisplayed=47.5k
R57 R151 R185: library part CMP-0026822-3, "RES, 0, 5%, 0.063 W, AEC-Q200 Grade 0, 0402", Manufacturer=Vishay-Dale, Power_W=63mW, Supplier Part Number 1=541-0.0JCT-ND, TempCo="200 ppm/C", Tolerance_%=5%, Value2=0.063W, Value_Code=0000, ValueDisplayed=0
R68 R79 R81 R86: library part CMP-0026491-2, "RES, 61.9, 1%, 0.063 W, AEC-Q200 Grade 0, 0402", Manufacturer=Vishay-Dale, Power_W=63mW, Supplier Part Number 1=541-61.9LCT-ND, TempCo="100 ppm/C", Tolerance_%=1%, Value2=0.063W, Value_Code=61R9, ValueDisplayed=61.9
R89: library part CMP-0026938-5, "RES, 4.7 k, 5%, 0.063 W, AEC-Q200 Grade 0, 0402", Manufacturer=Vishay-Dale, Power_W=63mW, Supplier Part Number 1=541-4.7KJCT-ND, TempCo="200 ppm/C", Tolerance_%=5%, Value2=0.063W, Value_Code=4k70, ValueDisplayed=4.7k
R90 R93 R176 R177 R187 R188: library part CMP-0027745-1, "RES, 4.99 k, 1%, 0.05 W, 0201", Manufacturer="Yageo America", Power_W=50mW, Supplier Part Number 1=YAG2712CT-ND, TempCo="200 ppm/C", Tolerance_%=1%, Value2=0.05W, Value_Code=4k99, ValueDisplayed=4.99k
R91 R92 R96 R97 R98 R180 R181 R198 R214: library part CMP-0086442-2, "RES SMD 0 OHM JUMPER 1/20W 0201", Manufacturer=Yageo, Power_W=50mW, TempCo=200ppm/°C, Tolerance_%=5%
R95 R100 R102 R123 R138 R165 R189 R190 R215: library part CMP-0088002-1, "10 kOhms ±0.5% 0.05W, 1/20W Chip Resistor 0201 (0603 Metric)  Thin Film", Manufacturer=Susumu, Power_W=50mW, TempCo=25ppm/°C, Tolerance_%=0.5%
R99 R212 R213: library part CMP-0027072-1, "RES, 220, 5%, 0.05 W, 0201", Manufacturer="Yageo America", Power_W=50mW, Supplier Part Number 1=311-220NCT-ND, TempCo="200 ppm/C", Tolerance_%=5%, Value2=0.05W, Value_Code=220R, ValueDisplayed=220
R118 R141 R171 R174: library part CMP-0027137-1, "RES, 510, 5%, 0.05 W, 0201", Manufacturer="Yageo America", Power_W=50mW, Supplier Part Number 1=YAG2907CT-ND, TempCo="200 ppm/C", Tolerance_%=5%, Value2=0.05W, Value_Code=510R, ValueDisplayed=510
R119 R120 R201: library part CMP-0027261-3, "RES, 100 k, 1%, 0.05 W, 0201", Manufacturer=Vishay-Dale, Power_W=50mW, Supplier Part Number 1=541-100KAABCT-ND, TempCo="100 ppm/C", Tolerance_%=1%, Value2=0.05W, Value_Code=100k
R121: library part CMP-0087183-1, "RES SMD 200 OHM 1% 1/5W 0402", Manufacturer="Vishay Dale", Power_W=200mW, TempCo=100ppm/°C, Tolerance_%=1%
R150 R169 R184: library part CMP-0026825-5, "RES, 10 k, 5%, 0.063 W, AEC-Q200 Grade 0, 0402", Manufacturer=Vishay-Dale, Power_W=63mW, Supplier Part Number 1=541-10KJCT-ND, TempCo="200 ppm/C", Tolerance_%=5%, Value2=0.063W, Value_Code=10k0, ValueDisplayed=10k
R153 R154 R155 R156 R182: library part CMP-0025950-3, "RES, 100 k, 1%, 0.063 W, AEC-Q200 Grade 0, 0402", Manufacturer=Vishay-Dale, Power_W=63mW, Supplier Part Number 1=541-100KLCT-ND, TempCo="100 ppm/C", Tolerance_%=1%, Value2=0.063W, Value_Code=100k
R172 R179: library part CMP-0078212-1, "RES, 510, 5%, 0.1 W, AEC-Q200 Grade 0, 0402", Manufacturer=Panasonic, Power_W=100mW, Supplier Part Number 1=P510JCT-ND, TempCo="200 ppm/C", Tolerance_%=5%, Value2=0.1W, Value_Code=510R, ValueDisplayed=510
R173 R175 R178 R183: library part CMP-0086444-2, "RES Thick Film SMD 3.83O 1% 1/16W 0402 200ppm/°C", Manufacturer=Yageo, Power_W=63mW, TempCo=200ppm/°C, Tolerance_%=1%
R186: library part CMP-0027052-1, "RES, 1.0 k, 5%, 0.05 W, 0201", Manufacturer="Yageo America", Power_W=50mW, Supplier Part Number 1=311-1KNCT-ND, TempCo="200 ppm/C", Tolerance_%=5%, Value2=0.05W, Value_Code=1k00, ValueDisplayed=1.0k
R191: library part CMP-0081973-1, "RES, 0, 0%, 0.25 W, AEC-Q200 Grade 0, 0603", Manufacturer=Vishay-Dale, Power_W=250mW, Supplier Part Number 1=541-2779-1-ND, Tolerance_%=0%, Value2=0.25W, Value_Code=0
R192 R193 R199 R200: library part CMP-0081623-1, "RES, 0.002, 1%, 1 W, AEC-Q200 Grade 0, 1206", Manufacturer=Rohm, Power_W=1W, Supplier Part Number 1=RHM.002ALCT-ND, TempCo="100 ppm/C", Tolerance_%=1%, Value_Code=2L000, ValueDisplayed=0.002
R194: library part CMP-0027452-1, "RES, 1.96 k, 1%, 0.05 W, 0201", Manufacturer="Yageo America", Power_W=50mW, Supplier Part Number 1=YAG2494CT-ND, TempCo="200 ppm/C", Tolerance_%=1%, Value2=0.05W, Value_Code=1k96, ValueDisplayed=1.96k
R196: library part CMP-0026944-3, "RES, 510, 5%, 0.063 W, AEC-Q200 Grade 0, 0402", Manufacturer=Vishay-Dale, Power_W=63mW, Supplier Part Number 1=541-510JCT-ND, TempCo="200 ppm/C", Tolerance_%=5%, Value2=0.063W, Value_Code=510R, ValueDisplayed=510
R197: library part CMP-0026659-1, "RES, 100 k, 1%, 0.1 W, 0402", Manufacturer=Panasonic, Power_W=100mW, TempCo="100 ppm/C", Tolerance_%=1%, Value2=0.1W, Value_Code=100k
R204 R207 R210: library part CMP-0026557-2, "RES, 7.87 k, 1%, 0.063 W, AEC-Q200 Grade 0, 0402", Manufacturer=Vishay-Dale, Power_W=63mW, Supplier Part Number 1=541-7.87KLCT-ND, TempCo="100 ppm/C", Tolerance_%=1%, Value2=0.063W, Value_Code=7k87, ValueDisplayed=7.87k
R205 R208 R211: library part CMP-0026574-2, "RES, 82.5 k, 1%, 0.063 W, AEC-Q200 Grade 0, 0402", Manufacturer=Vishay-Dale, Power_W=63mW, Supplier Part Number 1=541-82.5KLCT-ND, TempCo="100 ppm/C", Tolerance_%=1%, Value2=0.063W, Value_Code=82k5, ValueDisplayed=82.5k
S1: library part CMP-0002304-1, "Switch, SPST, Slide, Off-On, 6 Pos, 0.025A, 24V, SMD", CurrentRating_mA=25A, Manufacturer="CTS Electrocomponents", Supplier Part Number 1=CT2186LPST-ND
S2 S3: library part CMP-0002150-2, "SWITCH TACTILE SPST-NO 0.05A 12V", CurrentRating_mA=50A, Manufacturer="Omron Electronic Components", Supplier Part Number 1=SW1020CT-ND
TP1 TP8 TP9 TP10 TP11: library part CMP-0078143-3, "TEST POINT.  No entry in BOM.", Manufacturer=N/A
TP2 TP3 TP4 TP5 TP6 TP7: library part CMP-0003825-1, "1mm Test Point, SMT", Manufacturer=Any
TP12 TP13 TP14: library part CMP-0055138-1, "Test Point, Miniature, Black, TH", Color=Black, Manufacturer=Keystone, Supplier Part Number 1=36-5001-ND
U1: library part CMP-0081105-1, "IWR1843QAGABL, ABL0161B (FCBGA-161)", Alternate Manufacturer="Texas Instruments"
U2: library part CMP-0079267-1, "2.3V-3.6V, 16M-BIT [x 1/x 2/x 4] CMOS FLASH Memory, WSON-8", Manufacturer="Macronix International Co., LTD", Supplier Part Number 1=1092-1211-ND
U3: library part CMP-0067398-2, "Automotive Grade, 1.4V-Capable +/-0.5degC Temperature Sensor with Alert Function and I2C/SMBus, DRL0006A (SOT-OTHER-6)", Alternate Manufacturer="Texas Instruments"
U4: library part CMP-0079120-2, "4-A + 2.5-A + Two 1.5-A Buck Converters With Integrated Switches, RNF0026C (VQFN-HR-26)", Alternate Manufacturer="Texas Instruments", Alternate PartNumber=LP87524JRNFTQ1
U5 U12: library part CMP-0075992-1, "Automotive Fault Protected CAN Transceiver With Flexible Data-Rate, D0008A (SOIC-8)", Alternate Manufacturer="Texas Instruments", Alternate PartNumber=TCAN1042HGVDRQ1
U6 U7 U8 U10: library part CMP-0037978-1, "High-Side Measurement, Bi-Directional Current / Power Monitor with I2C Interface, 2.7 to 5.5 V, -40 to 125 degC, 10-pin SOP (DGS10), Green (RoHS & no Sb/Br)", Quiescent Current (+/-)(Typ)(mA)=0.33, Rating=Catalog
U9: library part CMP-0077265-1, "5.5-V, 2-A, 80 mohm Low Leakage Load Switch with RCB and Programmable Rise Time, DBV0006A (SOT-23-6)", Alternate Manufacturer="Texas Instruments", Alternate PartNumber=TPS22917DBVT
U11: library part CMP-0005309-2, "IC, EEPROM, 8KBIT, 400KHZ, 8SOIC", Manufacturer="ON Semiconductor", Supplier Part Number 1=CAT24C08WI-GT3CT-ND
U13: library part CMP-0067415-1, "10-Ohm Quad SPDT Analog Switch, RSV0016A (UQFN-16)", Alternate Manufacturer="Texas Instruments"
U14: library part CMP-0087172-1, "I/O Controller Interface IC USB to Dual UART bridge", Manufacturer="Silicon Labs"
U15: library part CMP-0074545-1, "Dual 10-ohm SPDT Analog Switch, RSE0010A (UQFN-10)", Alternate Manufacturer="Texas Instruments"
U16: library part CMP-0043358-3, "Dual In / Single Out Autoswitching Power Mux, 2.8 to 5.5 V, -40 to 85 degC, 8-pin SON (DRB), Green (RoHS & no Sb/Br)", IN1, IN2 Input Voltage(Max)(V)=5.5, IN1, IN2 Input Voltage(Min)(V)=2.8, IN1 Output Current(Max)(A)=1.25, Manufacturer="Texas Instruments"
U17: library part CMP-0051215-4, "Single 3-Input Positive-AND Gate, DSF0006A, LARGE T&R", F @ Nom Voltage(Max)(Mhz)=150, Generic Part Number=SN74LVC1G11, ICC @ Nom Voltage(Max)(mA)=0.01, Manufacturer="Texas Instruments", Operating Temperature Range(C)="-40 to 125,-40 to 85", Rating=Catalog, tpd @ Nom Voltage(Max)(ns)=20,7.8,6.2,4.6, Voltage(Nom)(V)=1.8,2.5,3.3,5
Y1: library part CMP-0004694-3, "Crystal, 40 MHz, 8pF, SMD", Frequency_Fixed=40MHz, Frequency Stability=+/-200ppm, Manufacturer=Kyocera, Supplier Part Number 1=581-CX3225SA40D0PTWC
ZZ1: library part CMP-0003616-3
ZZ2: library part CMP-0077236-1
ZZ3: library part CMP-0077237-1
ZZ4 ZZ5: library part CMP-0077238-1

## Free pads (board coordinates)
  round 157.48 hole 118.11: TH1(118.11,2248.99) TH2(118.11,1406.24) TH3(118.11,1087.57) TH4(118.11,339.54) TH5(2047.24,339.54) TH6(2047.24,1087.57) TH7(2047.24,1406.24) TH8(2047.24,2248.99)
  round 140 hole 80: TH9(576.76,1331.62)

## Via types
v1: diameter 13.77/15.74 (per signal layer), hole 5.9, Top Layer to L2_GND, tented both sides, 900 vias
v2: diameter 22.4, hole 12.2, Top Layer to Bottom Layer, tented both sides, 509 vias
v3: diameter 13.78/15.75 (per signal layer), hole 5.9, Top Layer to L2_GND, tented both sides, 72 vias
v4: diameter 18, hole 8, Top Layer to Bottom Layer, tented both sides, 71 vias
v5: diameter 22, hole 12.2, Top Layer to Bottom Layer, tented both sides, 57 vias
v6: diameter 25, hole 15, Top Layer to Bottom Layer, tented both sides, 28 vias
v7: diameter 19.68, hole 7.87, Top Layer to Bottom Layer, 16 vias
v8: diameter 13.77/15.74 (per signal layer), hole 5.9, Top Layer to L2_GND, tented top, 15 vias
v9: diameter 13.78/15.75 (per signal layer), hole 5.9, Top Layer to L2_GND, tented top, 1 vias

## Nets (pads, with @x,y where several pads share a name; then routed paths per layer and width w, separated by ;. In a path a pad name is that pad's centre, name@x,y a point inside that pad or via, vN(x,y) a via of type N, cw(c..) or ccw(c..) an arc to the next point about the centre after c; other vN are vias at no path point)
5V_IN: C68.1 C72.1 C73.1 C74.1 C75.1 D2.1 R69.2 R82.2 R90.1 R141.1 R174.1 R186.2 U4.9 U4.13 U4.18 U4.22 U4.26 | length 364.5
  Top Layer w9.84: R141.1@302.97,1116.87 308.78,1122.68 v2(308.78,1138.39)
  Top Layer w10: C75.1@950.83,200.89 950.83,223.3 960.96,233.43 U4.9@960.96,265.51 ; C74.1@950.83,451.39 950.83,428.98 960.96,418.85 U4.26@960.96,386.77 ; U4.13@1039.7,265.51 1039.7,233.43 1049.83,223.3 C73.1@1049.83,202.29 ; U4.22@1039.7,386.77 1039.7,418.85 1049.83,428.98 C72.1@1049.83,451.39
  Bottom Layer w15: v2(201.99,84.5) R82.2@201.99,129.09 ; R69.2@330.22,335.07 330.22,315.24 330.53,314.94 v2(332.34,314.94)
  other v2: 679.79,-258.11 679.82,-228.33 662.96,-183.19 610.5,-182.91 713.35,-131.1 165.35,111.32 1809.17,120.91 1849.47,124.48 162.78,152.06 1809.17,157.47 1849.29,159.53 1849.85,192.89 1809.17,193.14 1300.3,250.04 1329.54,255.23 1297.59,277.62 1335.18,280.54 1300.97,306.11 1333.95,307.04
  other v4: 920.36,194.17 1080.5,194.84 934.22,209.76 1066.79,210.64 1134.94,339.66 932.29,441.44 1067.6,443.6 921.03,458.3 1081.97,458.12
  other v6: 1778.08,240.49 1751.96,262.51 1801.21,265.47
5V_IN_SW: C51.1 L10.1 R118.1 U16.7 | length 31.9
  Top Layer w10: R118.1@1532.37,316.41 1539.45,309.33 v5(1561.35,309.33)
  other v2: 1650.14,244.33 1684.05,244.33 1672.31,276.25
5V_IN_USB: C46.2 C47.1 C49.1 C84.1 C85.1 D1.1 U16.6
  other v2: 1843.58,-265.3 1880.99,-265.09 1808.82,-264.07 1686.66,-262.97 1728.5,-262.8 1770.35,-262.5 1876.23,-234.87 1686.58,-227.4 1720.32,-227.18 1753.28,-226.14 1899.27,-208.38 1667.59,151.02 1707.59,157.78 1683.82,175.18 1655.26,177.05 1707.48,189.96 1675.7,203.99
A2: R161.1 R162.2 U11.3 | length 107.2
  Bottom Layer w6: U11.3@782.28,2026.43 840.32,2026.43 R161.1@850.32,2016.43 R162.2@850.32,1981.43
CAN1_RX: R80.1 U13.3 | length 105.5
  Top Layer w6: R80.1@538.88,257.94 563.02,257.94 590.27,285.18 611.78,285.18 616.24,280.73 U13.3@631.29,280.73
CAN1_TX: R78.1 U13.16 | length 172.4
  Top Layer w6: v2(579,337.48) 589.12,347.6 632.4,347.6 639.17,340.83 U13.16@639.17,335.85
  Bottom Layer w6: R78.1@528.88,257.94 554.72,283.79 554.72,313.2 v2(579,337.48)
CAN2_RX: R87.1 U13.9 | length 418.2
  Top Layer w6: R87.1@428.19,205.08 432.81,205.08 460.79,177.09 488.01,177.09 496.59,185.67 714.88,185.67 738.12,208.92 738.12,237.03 710.16,264.98 U13.9@694.28,264.98
CAN2_TX: R85.1 U13.12 | length 696.7
  Top Layer w6: R85.1@428.19,60.08 382.63,105.63 382.63,115.21 379.88,117.96 379.88,150.27 402.73,173.12 442.28,173.12 449.31,166.09 497.27,166.09 504.85,173.67 722.05,173.67 750.12,201.74 750.12,320.63 737.01,333.74 720.28,333.74 698.77,312.23 U13.12@694.28,312.23
CB_PMIC_1V0: C2.2 C3.2 J1.1 J1.3 L2.1 L3.1 R199.2 U7.9
  other v5: 1536.92,518.37 1657.89,518.6
  other v6: 445.8,1420.92 499.8,1436.09 446.03,1474.24 447.08,1520.63 489.76,1551.39 530.74,1576.08 728.76,1765.72 729.8,1801.55 687.8,1803.74 730.31,1832.57
CB_PMIC_1V2: C64.2 J1.5 J1.7 L7.1 R193.2 U8.9
  other v2: 819.72,228.41 784.61,235.94 819.27,258.44 785.5,267.46
  other v5: 531.47,1802.62 585.75,1847.06 617.61,1895.02 584.71,1940.63
CB_PMIC_1V8: C1.2 J1.9 L1.1 R192.2 R195.1 U6.9 | length 200.6
  Top Layer w10: U6.9@1323.04,374.27 1323.04,443.54 1411.63,532.13 R192.2@1417.66,532.13
  other v2: 1011.21,725.57 1030.65,748.13 993.86,758.33 1037.39,775.84 1008.64,781.2
  other v5: 1661.2,561.4 1678.37,579.14 1660.79,597.45
CONN_5V: C50.1 C92.1 C93.1 C94.1 C95.2 C96.2 C97.2 J1.2 J2.58 J2.59 J2.60 R102.1 R122.1 TP13.1 U16.8 | length 163.2
  Top Layer w25: v2(256.29,1127.59) 256.29,1107.32 259.45,1104.16 v2@277.2,1104.16 ; v2(666.86,-28.08) 666.86,-40.06 674.81,-48.01 v2(674.81,-72.03)
  Bottom Layer w15: v2@1092.45,-51.23 v2(1092.45,-27.49) ; v5(1385.91,229.68) v5@1385.91,253.61
  Bottom Layer w20: v2(1563.64,-41.98) 1567.5,-38.13 1567.5,-19.83 v2(1568.93,-18.4)
  other v2: 1091.96,-51.23 675,-49.36 256.29,1104.77 278.68,1104.16
  other v5: 1386.72,253.61
  other v6: 1719.16,383.04 1676.81,384.36 1758.2,385.29 1635.07,388.55 1809.94,482.31 1845.11,483.32
CONN_RS232RX: J6.55 R38.1 U15.7 | length 1968.5
  Top Layer w6: v2(1864.93,244.44) 1872.92,252.43 U15.7@1872.92,275.06
  L4_SIGNAL 2 w6: v5(1722.15,1195.52) 1722.15,1149.74 1710.89,1138.48 1710.89,1079.09 1741.74,1048.24 1770.68,1048.24 1823.59,995.33 1823.59,622.17 1927.74,518.02 1927.74,489.66 1954.21,463.19 1954.21,417.25 1926.5,389.55 1926.5,373.49 1864.93,311.92 v2(1864.93,244.44)
  Bottom Layer w6: J6.55@1465.8,34.94 1465.8,85.98 1478.49,98.66 1485.21,98.66 1490.06,103.52 1527.19,103.52 1537.16,93.55 1570.81,93.55 1607.64,56.71 1625.01,56.71 1670.38,11.35 1670.38,2.23 1687.3,-14.7 1831.81,-14.7 1884.25,37.75 1884.25,225.11 v2(1864.93,244.44) ; R38.1@1717.94,1250.43 1722.15,1246.21 v5(1722.15,1195.52)
CONN_RS232TX: J6.57 R40.1 U15.9 | length 2076.2
  Top Layer w6: U15.9@1912.29,275.06 1912.29,270.37 1915.45,267.21 1928.59,267.21 v2(1933.67,262.13)
  L4_SIGNAL 2 w6: v5(1749.67,1214.36) 1749.67,1191.86 1741.16,1183.36 1741.16,1151.79 1723.92,1134.54 1723.92,1083.03 1746.71,1060.24 1775.65,1060.24 1842.84,993.05 1842.84,654.37 1875.84,621.37 1892.62,621.37 1907.45,606.55 1907.45,562.06 1939.49,530.02 1939.49,496.37 1970.84,465.02 1970.84,418.32 1937.5,384.99 1937.5,360.66 1906.89,330.04 1906.89,288.91 v2(1933.67,262.13)
  Bottom Layer w6: J6.57@1485.49,34.94 1485.49,81.97 1495.03,91.52 1522.21,91.52 1532.19,81.55 1565.84,81.55 1602.67,44.71 1621.45,44.71 1658.38,7.79 1658.38,-36 1678.69,-56.31 1805.75,-56.31 1903.09,41.03 1903.09,165.53 1933.67,196.11 v2(1933.67,262.13) ; R40.1@1717.94,1288.81 1749.67,1257.08 v5(1749.67,1214.36)
EN_3V3: R195.2 R197.2 U9.3 | length 146.7
  Top Layer w10: v2(871.83,863) 871.83,832.06 871.6,831.84 U9.3@876.14,827.3 876.14,775.19 R195.2@893.75,757.58
  Bottom Layer w10: v2(871.83,863) 871.83,832.42 871.6,832.19 R197.2@872.36,831.43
